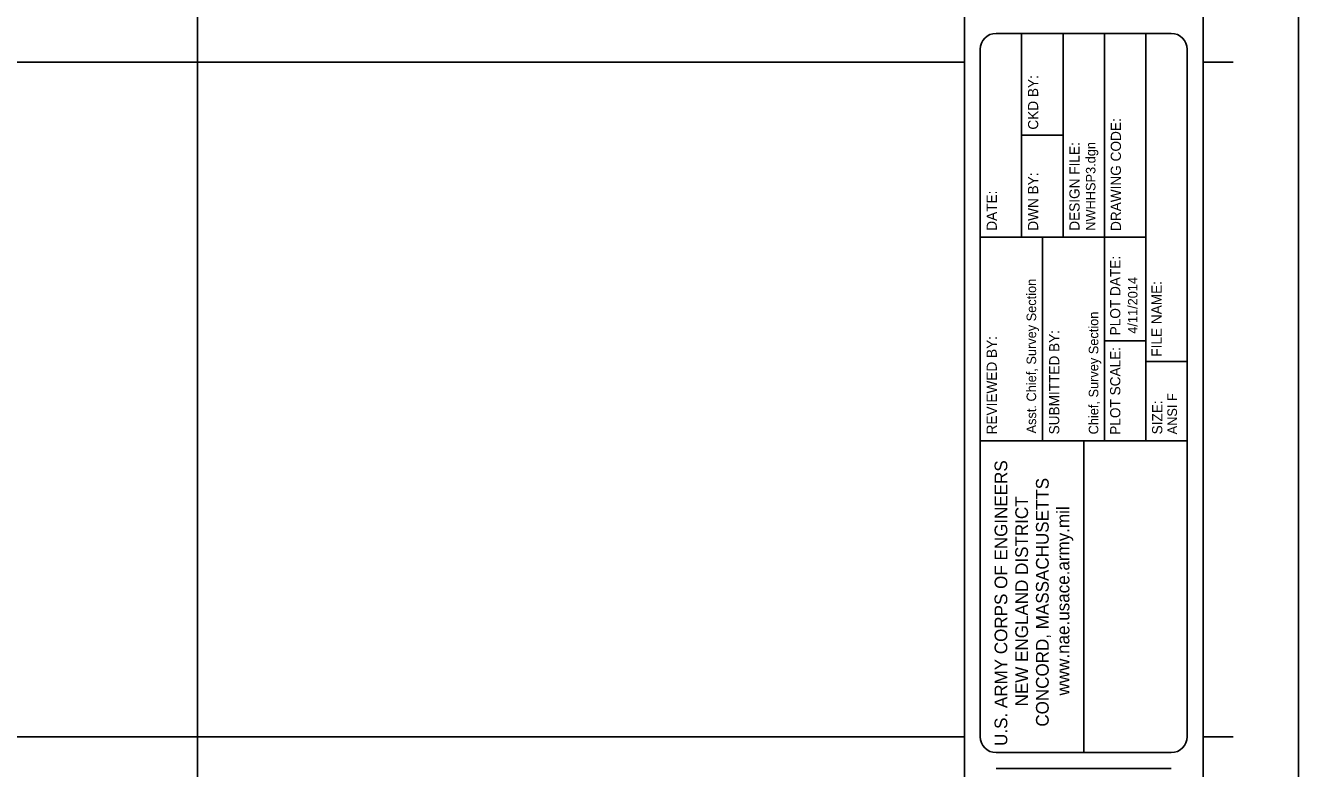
# Model space of a CAD drawing. Extents: x 0 to 3.33, y 0 to 2.33.
# Drawn here: x 2.5 to 3.333, y 0.483 to 0.97 of the extents above; entities that cross this region are included whole.
import ezdxf

# ---------------------------------------------------------------- set-up
doc = ezdxf.new("R2010")
doc.units = 0
for name, color, linetype in [('G-ANNO-NPLT', 7, 'Continuous'), ('G-ANNO-TEXT', 7, 'Continuous'), ('G-ANNO-TTLB', 7, 'Continuous'), ('G-ANNO-TTLB-GRID', 7, 'Continuous')]:
    doc.layers.add(name, color=color, linetype=linetype)

msp = doc.modelspace()

# ---------------------------------------------------------------- linework, layer by layer
at = {"layer": 'G-ANNO-NPLT'}
msp.add_lwpolyline([(0, 0), (3.33333, 0), (3.33333, 2.33333), (0, 2.33333)], close=True, dxfattribs=at)
at = {"layer": 'G-ANNO-TTLB'}
for p, q in [((3.15209, 0.83125), (3.15209, 0.96459)), ((3.17917, 0.83125), (3.17917, 0.96459)), ((3.20626, 0.69792), (3.20626, 0.96459)), ((3.23334, 0.69792), (3.23334, 0.96459)), ((3.12501, 0.50417), (3.12501, 0.95417)), ((3.29053, 0.94584), (3.27084, 0.94584)), ((3.17917, 0.89792), (3.15209, 0.89792)), ((3.15221, 0.83125), (3.12501, 0.83125)), ((3.17929, 0.83125), (3.15209, 0.83125)), ((3.16563, 0.69792), (3.16563, 0.83125)), ((3.20626, 0.83125), (3.17917, 0.83125)), ((3.23334, 0.83123), (3.20626, 0.83123)), ((3.23331, 0.76326), (3.20626, 0.76326)), ((3.26042, 0.74985), (3.23334, 0.74985)), ((3.12501, 0.69792), (3.26042, 0.69792)), ((3.19271, 0.49375), (3.19271, 0.69792)), ((3.29053, 0.50417), (3.27084, 0.50417))]:
    msp.add_line(p, q, dxfattribs=at)
for points in [[(0.12501, 0.0625), (3.11459, 0.0625), (3.11459, 2.27084), (0.12501, 2.27084)], [(3.11459, 0.0625), (3.27084, 0.0625), (3.27084, 2.27084), (3.11459, 2.27084)]]:
    msp.add_lwpolyline(points, close=True, dxfattribs=at)
for points in [[(3.25001, 0.96459), (3.13542, 0.96459)], [(3.25001, 0.96459), (3.13542, 0.96459)], [(3.25001, 0.96459), (3.13542, 0.96459)], [(3.26042, 0.50417), (3.26042, 0.95417)], [(3.25001, 0.49375), (3.13542, 0.49375)], [(3.13542, 0.48334), (3.25001, 0.48334)]]:
    msp.add_lwpolyline(points, dxfattribs=at)
for centre, start, end in [((3.13542, 0.95417), 90, 180), ((3.13542, 0.95417), 90, 180), ((3.13542, 0.95417), 90, 180), ((3.25001, 0.95417), 0, 90), ((3.25001, 0.95417), 0, 90), ((3.25001, 0.95417), 0, 90), ((3.13542, 0.50417), 180, 270), ((3.25001, 0.50417), 270, 0)]:
    msp.add_arc(centre, 0.01042, start, end, dxfattribs=at)
at = {"layer": 'G-ANNO-TTLB-GRID'}
for p, q in [((2.61251, 0.0625), (2.61251, 2.27084)), ((3.11459, 0.94584), (0.12501, 0.94584)), ((3.11459, 0.50417), (0.12501, 0.50417))]:
    msp.add_line(p, q, dxfattribs=at)

# ---------------------------------------------------------------- texts
at = {"layer": 'G-ANNO-TEXT'}
for s, height, p in [('CKD BY:', 0.006667, (3.16292, 0.90159)), ('DRAWING CODE:', 0.0066667, (3.21709, 0.83525)), ('DESIGN FILE:', 0.0066667, (3.19001, 0.83542)), ('DWN BY:', 0.006667, (3.16292, 0.83542)), ('DATE:', 0.006667, (3.13585, 0.83542)), ('PLOT DATE:', 0.006667, (3.21668, 0.76692)), ('Asst. Chief, Survey Section', 0.00625, (3.16157, 0.70271)), ('FILE NAME:', 0.006667, (3.24372, 0.75294)), ('Chief, Survey Section', 0.00625, (3.2023, 0.70209)), ('SUBMITTED BY:', 0.0066667, (3.17673, 0.70209)), ('REVIEWED BY:', 0.0066667, (3.13585, 0.70209)), ('PLOT SCALE:', 0.0066667, (3.21668, 0.70185)), ('SIZE:', 0.006667, (3.24417, 0.70209))]:
    msp.add_text(s, height=height, rotation=90, dxfattribs=at).set_placement(p)
at = {"layer": 'G-ANNO-TTLB'}
for s, height, p in [('NWHHSP3.dgn', 0.00625, (3.2004, 0.83543)), ('4/11/2014', 0.00625, (3.22791, 0.76796)), ('ANSI F', 0.00625, (3.25376, 0.70209)), ('U.S. ARMY CORPS OF ENGINEERS', 0.0083333, (3.14271, 0.49814)), ('CONCORD, MASSACHUSETTS', 0.0083333, (3.1698, 0.51076)), ('NEW ENGLAND DISTRICT', 0.0083333, (3.15626, 0.52403)), ('www.nae.usace.army.mil', 0.0083333, (3.18334, 0.53115))]:
    msp.add_text(s, height=height, rotation=90, dxfattribs=at).set_placement(p)

doc.saveas('drawing.dxf')
